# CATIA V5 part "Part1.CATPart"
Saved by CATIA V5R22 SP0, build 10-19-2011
Part number: Part1
Bounding box of the stored display mesh (mm): x -4 to 4, y -3.991 to 3.991, z 193.472 to 294.471
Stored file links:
  D:\PER\CAO_PER_MODIF_2025\CAO_PER_pick&place_2024P\Sous_Ensemble_Flacon\Verin\Part1.CATPart
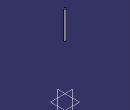
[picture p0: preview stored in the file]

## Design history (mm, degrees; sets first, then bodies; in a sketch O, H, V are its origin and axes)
Body1 (main body)
  DatumSurface1
  DatumSurface2
  DatumCurve1
  DatumSurface3
  DatumCurve2
  DatumCurve3
  Sketch1 on face of DatumSurface3, origin (0, 0, 194.4715), H (1, 0, 0), V (0, 1, 0)
    circle A1 centre (0, 0) radius 4
    reference projected arc E1 centre (0, 0) radius 4 from (-1.1533, -3.8301) to (1.1533, 3.8301) ccw from edge of DatumCurve3
    coincidence: A1 E1
  Pad1: profile Sketch1, direction (0, 0, 1), length 100, opposite side length 1
  Fillet1: radius 1, on edge [face of Pad1 from Sketch1.A1 | end face of Pad1]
